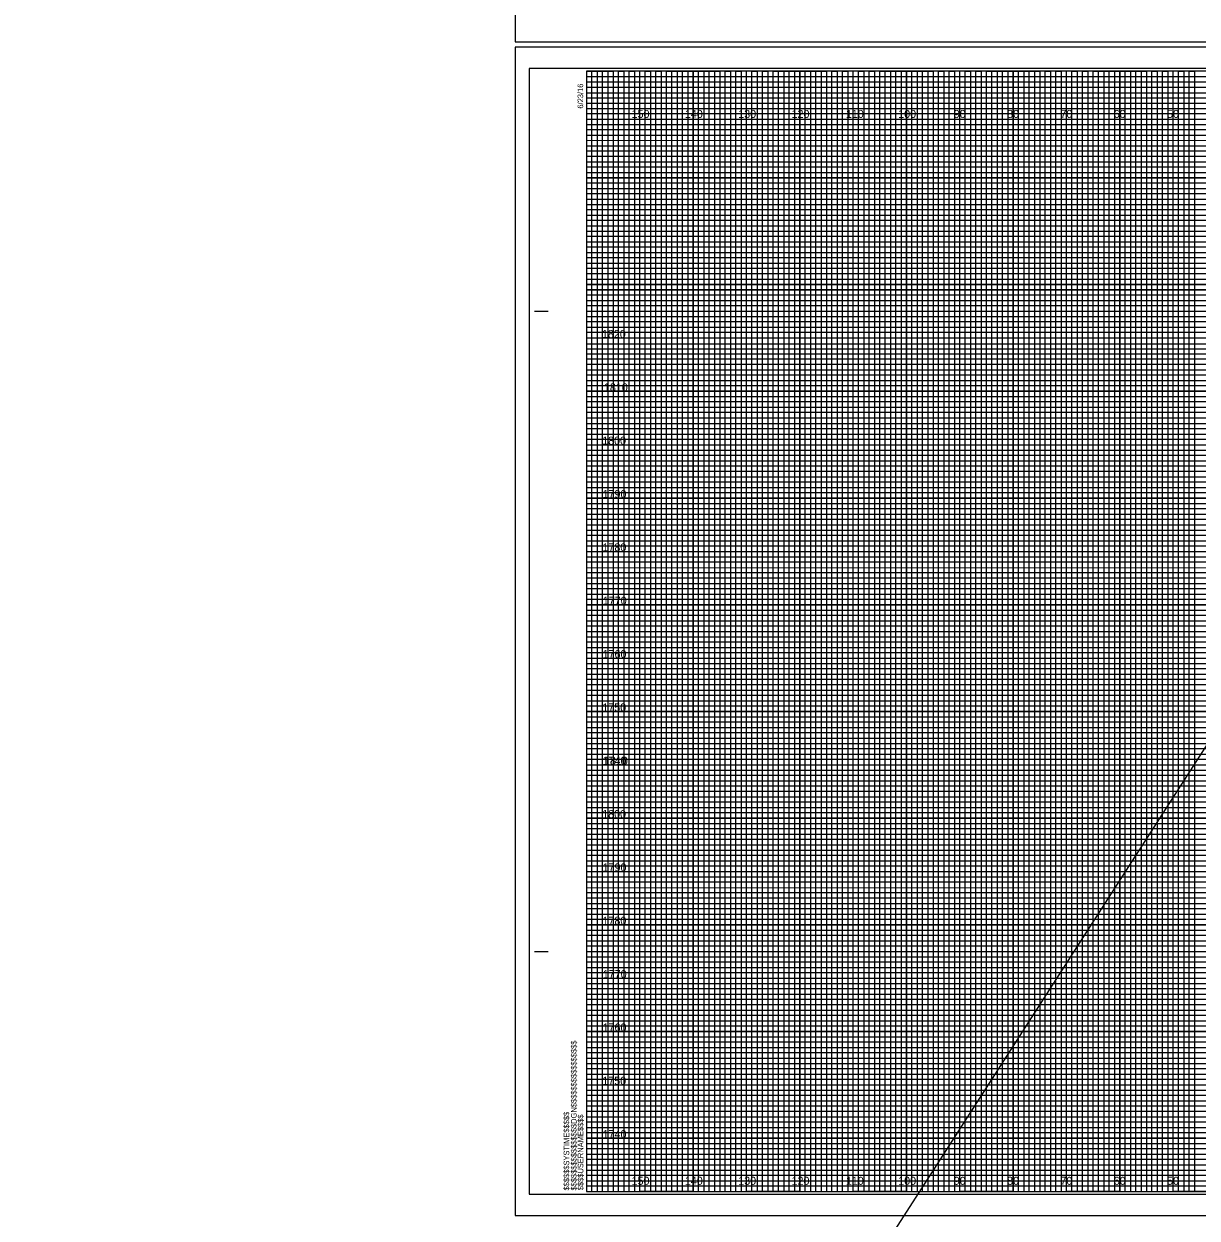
# Model space of a CAD drawing. Extents: x -419 to 4739, y -630 to 13534.
# Drawn here: x 384 to 604.1, y 1087.5 to 1311.4 of the extents above; entities that cross this region are included whole.
import ezdxf

# ---------------------------------------------------------------- set-up
doc = ezdxf.new("R2010")
doc.units = 0
for name, color, linetype in [('Old_Level_62', 7, 'Continuous'), ('Pattern 1', 7, 'Continuous'), ('Pattern 18', 7, 'Continuous'), ('Pattern 4', 7, 'Continuous'), ('Pattern 5', 7, 'Continuous'), ('Prop Dimension', 7, 'Continuous'), ('Prop Horizontal Alignment', 7, 'Continuous'), ('Raster_Level_0', 7, 'Continuous'), ('Scratch_Level_0', 7, 'Continuous'), ('Scratch_Level_3', 7, 'Continuous'), ('Scratch_Level_5', 7, 'Continuous')]:
    doc.layers.add(name, color=color, linetype=linetype)

msp = doc.modelspace()

# ---------------------------------------------------------------- linework, layer by layer
at = {"layer": 'Old_Level_62'}
for p, q in [((479.78, 1257.54), (482.28, 1257.54)), ((479.88, 1257.54), (482.38, 1257.54)), ((479.78, 1137.54), (482.28, 1137.54)), ((479.88, 1137.54), (482.38, 1137.54)), ((489.58, 1092.54), (489.58, 1092.54)), ((489.58, 1092.54), (489.58, 1092.54)), ((489.58, 1092.54), (489.58, 1092.54)), ((489.58, 1092.54), (489.58, 1092.54)), ((489.58, 1092.54), (489.58, 1092.54)), ((489.58, 1092.54), (489.58, 1092.54)), ((489.58, 1092.54), (489.58, 1092.54))]:
    msp.add_line(p, q, dxfattribs=at)
msp.add_lwpolyline([(809.58, 1302.54), (489.58, 1302.54), (489.58, 1092.54), (809.58, 1092.54)], close=True, dxfattribs=at)
at = {"layer": 'Pattern 18'}
msp.add_line((-419.01, -416.83), (1573.75, 2680.65), dxfattribs=at)
for points in [[(476.18, 1308.04), (812.88, 1308.04), (812.88, 1527.04), (476.18, 1527.04)], [(476.18, 1088.04), (812.88, 1088.04), (812.88, 1307.04), (476.18, 1307.04)]]:
    msp.add_lwpolyline(points, close=True, dxfattribs=at)
at = {"layer": 'Pattern 4'}
for p, q in [((489.58, 1301.54), (749.58, 1301.54)), ((749.58, 1300.52), (489.58, 1300.52)), ((489.58, 1300.52), (489.58, 1299.54)), ((489.58, 1299.54), (749.58, 1299.54)), ((749.58, 1298.43), (489.58, 1298.43)), ((489.58, 1298.43), (489.58, 1296.54)), ((489.58, 1296.54), (809.58, 1296.54))]:
    msp.add_line(p, q, dxfattribs=at)
for points in [[(489.58, 1295.54), (759.58, 1295.54), (809.58, 1295.54), (809.58, 1294.54), (489.58, 1294.54)], [(489.58, 1293.54), (809.58, 1293.54), (809.58, 1291.54), (489.58, 1291.54)], [(489.58, 1290.54), (809.58, 1290.54), (809.58, 1289.54), (489.58, 1289.52)], [(489.58, 1288.54), (809.58, 1288.54), (809.58, 1286.54), (489.58, 1286.54)], [(489.58, 1285.54), (809.58, 1285.54), (809.58, 1284.54), (489.58, 1284.54)], [(489.58, 1283.54), (809.58, 1283.54), (809.58, 1281.54), (489.58, 1281.54)], [(489.58, 1280.54), (809.58, 1280.54), (809.58, 1279.54), (489.58, 1279.54)], [(489.58, 1278.54), (809.58, 1278.54), (809.58, 1276.54), (489.58, 1276.54)], [(489.58, 1275.54), (809.58, 1275.54), (809.58, 1274.54), (489.58, 1274.54)], [(489.58, 1273.54), (809.58, 1273.54), (809.58, 1271.54), (489.58, 1271.54)], [(489.58, 1270.54), (809.58, 1270.54), (809.58, 1269.54), (489.58, 1269.54)], [(489.58, 1268.54), (809.58, 1268.54), (809.58, 1266.49), (809.58, 1265.54), (809.58, 1264.54), (489.58, 1264.54)], [(489.58, 1266.54), (809.58, 1266.54), (809.58, 1265.54), (489.58, 1265.54)], [(489.58, 1263.54), (809.58, 1263.54), (809.58, 1261.54), (489.58, 1261.57)], [(489.58, 1261.57), (809.58, 1261.54), (809.58, 1260.54), (489.58, 1260.54)], [(489.58, 1259.54), (809.58, 1259.54), (809.58, 1258.54), (489.58, 1258.54)], [(489.58, 1256.54), (809.58, 1256.54), (809.58, 1255.54), (489.58, 1255.54)], [(489.58, 1254.54), (809.58, 1254.54), (809.58, 1253.54), (489.58, 1253.54)], [(489.51, 1251.43), (809.58, 1251.43), (809.58, 1250.42), (489.51, 1250.42)], [(489.58, 1249.54), (809.58, 1249.54), (809.58, 1248.54), (489.58, 1248.54)], [(489.58, 1246.54), (809.58, 1246.54), (809.58, 1245.54), (489.58, 1245.54)], [(489.58, 1244.54), (809.58, 1244.54), (809.58, 1243.54), (489.58, 1243.54)], [(489.58, 1241.54), (809.58, 1241.54), (809.58, 1240.54), (489.58, 1240.54)], [(489.58, 1239.54), (809.58, 1239.54), (809.58, 1238.54), (489.58, 1238.54)], [(489.58, 1236.54), (809.58, 1236.54), (809.58, 1235.54), (489.58, 1235.54)], [(489.58, 1234.54), (809.58, 1234.54), (809.58, 1233.54), (489.58, 1233.54)], [(489.58, 1231.54), (809.58, 1231.54), (809.57, 1230.52), (489.58, 1230.54)], [(489.58, 1229.54), (809.58, 1229.54), (809.58, 1228.54), (489.58, 1228.54)], [(489.58, 1226.54), (809.58, 1226.54), (809.58, 1225.54), (489.58, 1225.54)], [(489.58, 1224.54), (809.58, 1224.54), (809.58, 1223.54), (489.58, 1223.54)], [(489.58, 1221.54), (809.58, 1221.54), (809.58, 1220.54), (489.58, 1220.54)], [(489.58, 1219.54), (809.58, 1219.54), (809.58, 1218.54), (489.58, 1218.54)], [(489.58, 1216.54), (809.58, 1216.54), (809.58, 1215.54), (489.58, 1215.54)], [(489.58, 1214.54), (809.58, 1214.54), (809.58, 1213.54), (489.58, 1213.54)], [(489.58, 1211.54), (809.58, 1211.54), (809.58, 1210.54), (489.58, 1210.54)], [(489.58, 1209.53), (809.65, 1209.45), (809.58, 1208.54), (489.58, 1208.54)], [(489.58, 1206.54), (809.58, 1206.54), (809.58, 1205.54), (489.58, 1205.54)], [(489.58, 1204.54), (809.58, 1204.54), (809.58, 1203.54), (489.58, 1203.54)], [(489.58, 1201.54), (809.58, 1201.54), (809.58, 1200.54), (489.58, 1200.54)], [(489.58, 1199.54), (809.58, 1199.54), (809.58, 1198.54), (489.58, 1198.54)], [(489.58, 1196.54), (809.58, 1196.54), (809.58, 1195.54), (489.58, 1195.54)], [(489.58, 1194.54), (809.58, 1194.54), (809.58, 1193.54), (489.58, 1193.54)], [(489.58, 1191.54), (809.58, 1191.54), (809.58, 1190.54), (489.58, 1190.54)], [(489.58, 1189.54), (809.58, 1189.54), (809.58, 1188.54), (489.58, 1188.54)], [(489.58, 1186.54), (809.58, 1186.54), (809.58, 1185.54), (489.58, 1185.54)], [(489.58, 1184.54), (809.58, 1184.54), (809.58, 1183.54), (489.58, 1183.54)], [(489.58, 1181.54), (809.58, 1181.54), (809.58, 1180.54), (489.58, 1180.54)], [(489.58, 1179.54), (809.58, 1179.54), (809.58, 1178.54), (489.58, 1178.54)], [(489.58, 1176.54), (809.58, 1176.54), (809.58, 1175.54), (489.58, 1175.54)], [(489.58, 1174.54), (809.58, 1174.54), (809.58, 1173.54), (489.58, 1173.54)], [(489.58, 1171.54), (809.58, 1171.54), (809.57, 1170.52), (489.58, 1170.54)], [(489.58, 1169.54), (809.58, 1169.54), (809.58, 1168.54), (489.58, 1168.54)], [(489.58, 1166.54), (809.58, 1166.54), (809.58, 1165.54), (489.58, 1165.54)], [(489.58, 1164.54), (809.58, 1164.54), (809.58, 1163.54), (489.58, 1163.54)], [(489.58, 1161.54), (809.58, 1161.54), (809.58, 1160.54), (489.58, 1160.54)], [(489.58, 1159.54), (809.58, 1159.54), (809.58, 1158.54), (489.58, 1158.54)], [(489.58, 1156.54), (809.58, 1156.54), (809.58, 1155.54), (489.58, 1155.54)], [(489.58, 1154.54), (809.58, 1154.54), (809.58, 1153.54), (489.58, 1153.54)], [(489.58, 1151.54), (809.58, 1151.54), (809.58, 1150.54), (489.58, 1150.54)], [(489.58, 1149.53), (809.65, 1149.45), (809.58, 1148.54), (489.58, 1148.54)], [(489.58, 1146.54), (809.58, 1146.54), (809.58, 1145.54), (489.58, 1145.54)], [(489.58, 1144.54), (809.58, 1144.54), (809.58, 1143.54), (489.58, 1143.54)], [(489.58, 1141.54), (809.58, 1141.54), (809.58, 1140.54), (489.58, 1140.54)], [(489.58, 1139.54), (809.58, 1139.54), (809.58, 1138.54), (489.58, 1138.54)], [(489.58, 1136.54), (809.58, 1136.54), (809.58, 1135.54), (489.58, 1135.54)], [(489.58, 1134.54), (809.58, 1134.54), (809.58, 1133.54), (489.58, 1133.54)], [(489.58, 1131.54), (809.58, 1131.54), (809.58, 1130.54), (489.58, 1130.54)], [(489.58, 1129.54), (809.58, 1129.54), (809.58, 1128.54), (489.58, 1128.54)], [(489.58, 1126.54), (809.58, 1126.54), (809.58, 1125.54), (489.58, 1125.54)], [(489.58, 1124.54), (809.58, 1124.54), (809.58, 1123.54), (489.58, 1123.54)], [(489.58, 1121.54), (809.58, 1121.54), (809.58, 1120.54), (489.58, 1120.54)], [(489.58, 1119.54), (809.58, 1119.54), (809.58, 1118.54), (489.58, 1118.54)], [(489.58, 1116.54), (809.58, 1116.54), (809.58, 1115.54), (489.58, 1115.54)], [(489.58, 1114.54), (809.58, 1114.54), (809.58, 1113.54), (489.58, 1113.54)], [(489.58, 1111.54), (809.58, 1111.54), (809.58, 1110.54), (489.58, 1110.54)], [(489.58, 1109.54), (809.58, 1109.54), (809.58, 1108.54), (489.58, 1108.54)], [(489.58, 1106.54), (809.58, 1106.54), (809.58, 1105.54), (489.58, 1105.54)], [(489.58, 1104.54), (809.58, 1104.54), (809.58, 1103.54), (489.58, 1103.54)], [(489.58, 1101.54), (809.58, 1101.54), (809.58, 1100.54), (489.58, 1100.54)], [(489.58, 1099.54), (809.58, 1099.54), (809.58, 1098.54), (489.58, 1098.54)], [(489.58, 1096.54), (809.58, 1096.54), (809.58, 1095.54), (489.58, 1095.54)], [(489.58, 1094.54), (809.58, 1094.54), (809.58, 1093.54), (489.58, 1093.54)]]:
    msp.add_lwpolyline(points, dxfattribs=at)
at = {"layer": 'Pattern 5'}
for p, q in [((476.18, 1527.04), (476.18, 1308.04)), ((476.18, 1308.04), (812.88, 1308.04)), ((812.88, 1307.04), (476.18, 1307.04)), ((476.18, 1307.04), (476.18, 1088.04)), ((476.18, 1088.04), (812.88, 1088.04))]:
    msp.add_line(p, q, dxfattribs=at)
at = {"layer": 'Prop Dimension'}
for points in [[(489.58, 1092.54), (490.58, 1092.54), (490.58, 1302.54), (491.58, 1302.54), (491.58, 1092.54)], [(491.58, 1092.54), (492.58, 1092.54), (492.58, 1302.54), (493.58, 1302.54), (493.58, 1092.54)], [(494.58, 1092.54), (495.58, 1092.54), (495.58, 1302.54), (496.58, 1302.54), (496.58, 1092.54)], [(496.58, 1092.54), (497.58, 1092.54), (497.58, 1302.54), (498.58, 1302.54), (498.58, 1092.54)], [(499.58, 1092.54), (500.58, 1092.54), (500.58, 1302.54), (501.58, 1302.54), (501.58, 1092.54)], [(501.58, 1092.54), (502.58, 1092.54), (502.58, 1302.54), (503.58, 1302.54), (503.58, 1092.54)], [(504.58, 1092.54), (505.58, 1092.54), (505.58, 1302.54), (506.58, 1302.54), (506.58, 1092.54)], [(506.58, 1092.54), (507.58, 1092.54), (507.58, 1302.54), (508.58, 1302.54), (508.58, 1092.54)], [(509.58, 1092.54), (510.58, 1092.54), (510.58, 1302.54), (511.58, 1302.54), (511.58, 1092.54)], [(511.58, 1092.54), (512.58, 1092.54), (512.58, 1302.54), (513.58, 1302.54), (513.58, 1092.54)], [(514.58, 1092.54), (515.58, 1092.54), (515.58, 1302.54), (516.58, 1302.54), (516.58, 1092.54)], [(516.58, 1092.54), (517.58, 1092.54), (517.58, 1302.54), (518.58, 1302.54), (518.58, 1092.54)], [(519.58, 1092.54), (520.58, 1092.54), (520.58, 1302.54), (521.58, 1302.54), (521.58, 1092.54)], [(521.58, 1092.54), (522.58, 1092.54), (522.58, 1302.54), (523.58, 1302.54), (523.58, 1092.54)], [(524.58, 1092.54), (525.58, 1092.54), (525.58, 1302.54), (526.58, 1302.54), (526.58, 1092.54)], [(526.58, 1092.54), (527.58, 1092.54), (527.58, 1302.54), (528.58, 1302.54), (528.58, 1092.54)], [(529.58, 1092.54), (530.58, 1092.54), (530.58, 1302.54), (531.58, 1302.54), (531.58, 1092.54)], [(531.58, 1092.54), (532.58, 1092.54), (532.58, 1302.54), (533.58, 1302.54), (533.58, 1092.54)], [(534.58, 1092.54), (535.58, 1092.54), (535.58, 1302.54), (536.58, 1302.54), (536.58, 1092.54)], [(536.58, 1092.54), (537.58, 1092.54), (537.58, 1302.54), (538.58, 1302.54), (538.58, 1092.54)], [(539.58, 1092.54), (540.58, 1092.54), (540.58, 1302.54), (541.58, 1302.54), (541.58, 1092.54)], [(541.58, 1092.54), (542.58, 1092.54), (542.58, 1302.54), (543.58, 1302.54), (543.58, 1092.54)], [(544.58, 1092.54), (545.58, 1092.54), (545.58, 1302.54), (546.58, 1302.54), (546.58, 1092.54)], [(546.58, 1092.54), (547.58, 1092.54), (547.58, 1302.54), (548.58, 1302.54), (548.58, 1092.54)], [(549.58, 1092.54), (550.58, 1092.54), (550.58, 1302.54), (551.58, 1302.54), (551.58, 1092.54)], [(551.58, 1092.54), (552.58, 1092.54), (552.58, 1302.54), (553.58, 1302.54), (553.58, 1092.54)], [(554.58, 1092.54), (555.58, 1092.54), (555.58, 1302.54), (556.58, 1302.54), (556.58, 1092.54)], [(556.58, 1092.54), (557.58, 1092.54), (557.58, 1302.54), (558.58, 1302.54), (558.58, 1092.54)], [(559.58, 1092.54), (560.58, 1092.54), (560.58, 1302.54), (561.58, 1302.54), (561.58, 1092.54)], [(561.58, 1092.54), (562.58, 1092.54), (562.58, 1302.54), (563.58, 1302.54), (563.58, 1092.54)], [(564.58, 1092.54), (565.58, 1092.54), (565.58, 1302.54), (566.58, 1302.54), (566.58, 1092.54)], [(566.58, 1092.54), (567.58, 1092.54), (567.58, 1302.54), (568.58, 1302.54), (568.58, 1092.54)], [(569.58, 1092.54), (570.58, 1092.54), (570.58, 1302.54), (571.58, 1302.54), (571.58, 1092.54)], [(571.58, 1092.54), (572.58, 1092.54), (572.58, 1302.54), (573.58, 1302.54), (573.58, 1092.54)], [(574.58, 1092.54), (575.58, 1092.54), (575.58, 1302.54), (576.58, 1302.54), (576.58, 1092.54)], [(576.58, 1092.54), (577.58, 1092.54), (577.58, 1302.54), (578.58, 1302.54), (578.58, 1092.54)], [(579.58, 1092.54), (580.58, 1092.54), (580.58, 1302.54), (581.58, 1302.54), (581.58, 1092.54)], [(581.58, 1092.54), (582.58, 1092.54), (582.58, 1302.54), (583.58, 1302.54), (583.58, 1092.54)], [(584.58, 1092.54), (585.58, 1092.54), (585.58, 1302.54), (586.58, 1302.54), (586.58, 1092.54)], [(586.58, 1092.54), (587.58, 1092.54), (587.58, 1302.54), (588.58, 1302.54), (588.58, 1092.54)], [(589.58, 1092.54), (590.58, 1092.54), (590.58, 1302.54), (591.58, 1302.54), (591.58, 1092.54)], [(591.58, 1092.54), (592.58, 1092.54), (592.58, 1302.54), (593.58, 1302.54), (593.58, 1092.54)], [(594.58, 1092.54), (595.58, 1092.54), (595.58, 1302.54), (596.58, 1302.54), (596.58, 1092.54)], [(596.58, 1092.54), (597.58, 1092.54), (597.58, 1302.54), (598.58, 1302.54), (598.58, 1092.54)], [(599.58, 1092.54), (600.58, 1092.54), (600.58, 1302.54), (601.58, 1302.54), (601.58, 1092.54)], [(601.58, 1092.54), (602.58, 1092.54), (602.58, 1302.54), (603.58, 1302.54), (603.58, 1092.54)]]:
    msp.add_lwpolyline(points, dxfattribs=at)
at = {"layer": 'Prop Horizontal Alignment'}
for points in [[(489.58, 1302.54), (494.58, 1302.54), (494.58, 1092.54), (504.58, 1092.54), (504.58, 1302.54), (514.58, 1302.54), (514.58, 1092.54), (524.58, 1092.54), (524.58, 1302.54), (534.58, 1302.54), (534.58, 1092.54), (544.58, 1092.54), (544.58, 1302.54), (554.58, 1302.54), (554.58, 1092.54), (564.58, 1092.54), (564.58, 1302.54), (574.58, 1302.54), (574.58, 1092.54), (584.58, 1092.54), (584.58, 1302.54), (594.58, 1302.54), (594.58, 1092.54), (604.58, 1092.54)], [(489.58, 1297.54), (764.58, 1297.54)], [(489.58, 1277.54), (809.58, 1277.54), (809.58, 1287.54), (489.58, 1287.54)], [(489.58, 1257.54), (809.58, 1257.54), (809.58, 1267.54), (489.58, 1267.54)], [(489.58, 1237.54), (809.58, 1237.54), (809.58, 1247.54), (489.58, 1247.54)], [(489.58, 1217.54), (809.58, 1217.54), (809.58, 1227.54), (489.58, 1227.54)], [(489.58, 1197.54), (809.58, 1197.54), (809.58, 1207.54), (489.58, 1207.54)], [(489.58, 1177.54), (809.58, 1177.54), (809.58, 1187.54), (489.58, 1187.54)], [(489.58, 1157.54), (809.58, 1157.54), (809.58, 1167.54), (489.58, 1167.54)], [(489.58, 1137.54), (809.58, 1137.54), (809.58, 1147.54), (489.58, 1147.54)], [(489.58, 1117.54), (809.58, 1117.54), (809.58, 1127.54), (489.58, 1127.54)], [(489.58, 1097.54), (809.58, 1097.54), (809.58, 1107.54), (489.58, 1107.54)]]:
    msp.add_lwpolyline(points, dxfattribs=at)
at = {"layer": 'Scratch_Level_0'}
for p, q in [((499.58, 1092.54), (499.58, 1302.54)), ((509.58, 1092.54), (509.58, 1302.54)), ((519.58, 1092.54), (519.58, 1302.54)), ((529.58, 1092.54), (529.58, 1302.54)), ((539.58, 1092.54), (539.58, 1302.54)), ((549.58, 1092.54), (549.58, 1302.54)), ((559.58, 1092.54), (559.58, 1302.54)), ((569.58, 1092.54), (569.58, 1302.54)), ((579.58, 1092.54), (579.58, 1302.54)), ((589.58, 1092.54), (589.58, 1302.54)), ((599.58, 1092.54), (599.58, 1302.54)), ((489.58, 1292.54), (809.58, 1292.54)), ((489.58, 1282.54), (809.58, 1282.54)), ((489.58, 1272.54), (809.58, 1272.54)), ((489.58, 1262.54), (809.58, 1262.54)), ((489.58, 1252.54), (809.58, 1252.54)), ((489.58, 1242.54), (809.58, 1242.54)), ((489.58, 1232.54), (809.58, 1232.54)), ((489.58, 1222.54), (809.58, 1222.54)), ((489.58, 1212.54), (809.58, 1212.54)), ((489.58, 1202.54), (809.58, 1202.54)), ((489.58, 1192.54), (809.58, 1192.54)), ((489.58, 1182.54), (809.58, 1182.54)), ((489.58, 1172.54), (809.58, 1172.54)), ((489.58, 1162.54), (809.58, 1162.54)), ((489.58, 1152.54), (809.58, 1152.54)), ((489.58, 1142.54), (809.58, 1142.54)), ((489.58, 1132.54), (809.58, 1132.54)), ((489.58, 1122.54), (809.58, 1122.54)), ((489.58, 1112.54), (809.58, 1112.54)), ((489.58, 1102.54), (809.58, 1102.54))]:
    msp.add_line(p, q, dxfattribs=at)
at = {"layer": 'Scratch_Level_3'}
for p, q in [((499.58, 1302.54), (489.58, 1302.54)), ((499.58, 1092.54), (499.58, 1302.54)), ((519.58, 1302.54), (509.58, 1302.54)), ((509.58, 1302.54), (509.58, 1092.54)), ((519.58, 1092.54), (519.58, 1302.54)), ((539.58, 1302.54), (529.58, 1302.54)), ((529.58, 1302.54), (529.58, 1092.54)), ((539.58, 1092.54), (539.58, 1302.54)), ((559.58, 1302.54), (549.58, 1302.54)), ((549.58, 1302.54), (549.58, 1092.54)), ((559.58, 1092.54), (559.58, 1302.54)), ((579.58, 1302.54), (569.58, 1302.54)), ((569.58, 1302.54), (569.58, 1092.54)), ((579.58, 1092.54), (579.58, 1302.54)), ((599.58, 1302.54), (589.58, 1302.54)), ((589.58, 1302.54), (589.58, 1092.54)), ((599.58, 1092.54), (599.58, 1302.54)), ((509.58, 1092.54), (499.58, 1092.54)), ((529.58, 1092.54), (519.58, 1092.54)), ((549.58, 1092.54), (539.58, 1092.54)), ((569.58, 1092.54), (559.58, 1092.54)), ((589.58, 1092.54), (579.58, 1092.54)), ((609.58, 1092.54), (599.58, 1092.54))]:
    msp.add_line(p, q, dxfattribs=at)
for points in [[(489.58, 1292.54), (809.58, 1292.54), (809.58, 1282.54), (489.58, 1282.54)], [(489.58, 1272.54), (809.58, 1272.54), (809.58, 1262.54), (489.58, 1262.54)], [(489.58, 1252.54), (809.58, 1252.54), (809.58, 1242.54), (489.58, 1242.54)], [(489.58, 1232.54), (809.58, 1232.54), (809.58, 1222.54), (489.58, 1222.54)], [(489.58, 1212.54), (809.58, 1212.54), (809.58, 1202.54), (489.58, 1202.54)], [(489.58, 1192.54), (809.58, 1192.54), (809.58, 1182.54), (489.58, 1182.54)], [(489.58, 1172.54), (809.58, 1172.54), (809.58, 1162.54), (489.58, 1162.54)], [(489.58, 1152.54), (809.58, 1152.54), (809.58, 1142.54), (489.58, 1142.54)], [(489.58, 1132.54), (809.58, 1132.54), (809.58, 1122.54), (489.58, 1122.54)], [(489.58, 1112.54), (809.58, 1112.54), (809.58, 1102.54), (489.58, 1102.54)]]:
    msp.add_lwpolyline(points, dxfattribs=at)
at = {"layer": 'Scratch_Level_5'}
msp.add_lwpolyline([(478.78, 1092.04), (811.98, 1092.04), (811.98, 1303.04), (478.78, 1303.04)], close=True, dxfattribs=at)

# ---------------------------------------------------------------- texts
at = {"layer": 'Old_Level_62'}
for s, p in [('6/23/16', (488.93, 1295.54)), ('$$$$$$$$$$$$$$$$DGN$$$$$$$$$$$$$$$$', (487.7, 1092.72)), ('$$$$$$SYSTIME$$$$$', (486.32, 1092.72)), ('$$$$USERNAME$$$$', (488.96, 1092.77))]:
    msp.add_text(s, height=1.05, rotation=90, dxfattribs=at).set_placement(p)
at = {"layer": 'Pattern 1'}
for s, p in [('1820', (492.45, 1252.54)), ('1810', (492.83, 1242.54)), ('1800', (492.5, 1232.54)), ('1790', (492.58, 1222.54)), ('1780', (492.56, 1212.54)), ('1770', (492.62, 1202.54)), ('1760', (492.58, 1192.54)), ('1750', (492.53, 1182.54)), ('1740', (492.58, 1172.54)), ('1810', (492.83, 1172.54)), ('1800', (492.5, 1162.54)), ('1790', (492.58, 1152.54)), ('1780', (492.56, 1142.54)), ('1770', (492.62, 1132.54)), ('1760', (492.58, 1122.54)), ('1750', (492.53, 1112.54)), ('1740', (492.58, 1102.54))]:
    msp.add_text(s, height=1.5, dxfattribs=at).set_placement(p)
at = {"layer": 'Raster_Level_0'}
for s, p in [('150', (498.02, 1293.79)), ('140', (508.02, 1293.79)), ('130', (518.02, 1293.79)), ('120', (528.02, 1293.79)), ('110', (538.2, 1293.79)), ('100', (548.02, 1293.79)), ('90', (558.44, 1293.79)), ('80', (568.44, 1293.79)), ('70', (578.44, 1293.79)), ('60', (588.44, 1293.79)), ('50', (598.44, 1293.79)), ('150', (498.02, 1093.79)), ('140', (508.02, 1093.79)), ('130', (518.02, 1093.79)), ('120', (528.02, 1093.79)), ('110', (538.2, 1093.79)), ('100', (548.02, 1093.79)), ('90', (558.44, 1093.79)), ('80', (568.44, 1093.79)), ('70', (578.44, 1093.79)), ('60', (588.44, 1093.79)), ('50', (598.44, 1093.79))]:
    msp.add_text(s, height=1.5, dxfattribs=at).set_placement(p)

doc.saveas('drawing.dxf')
